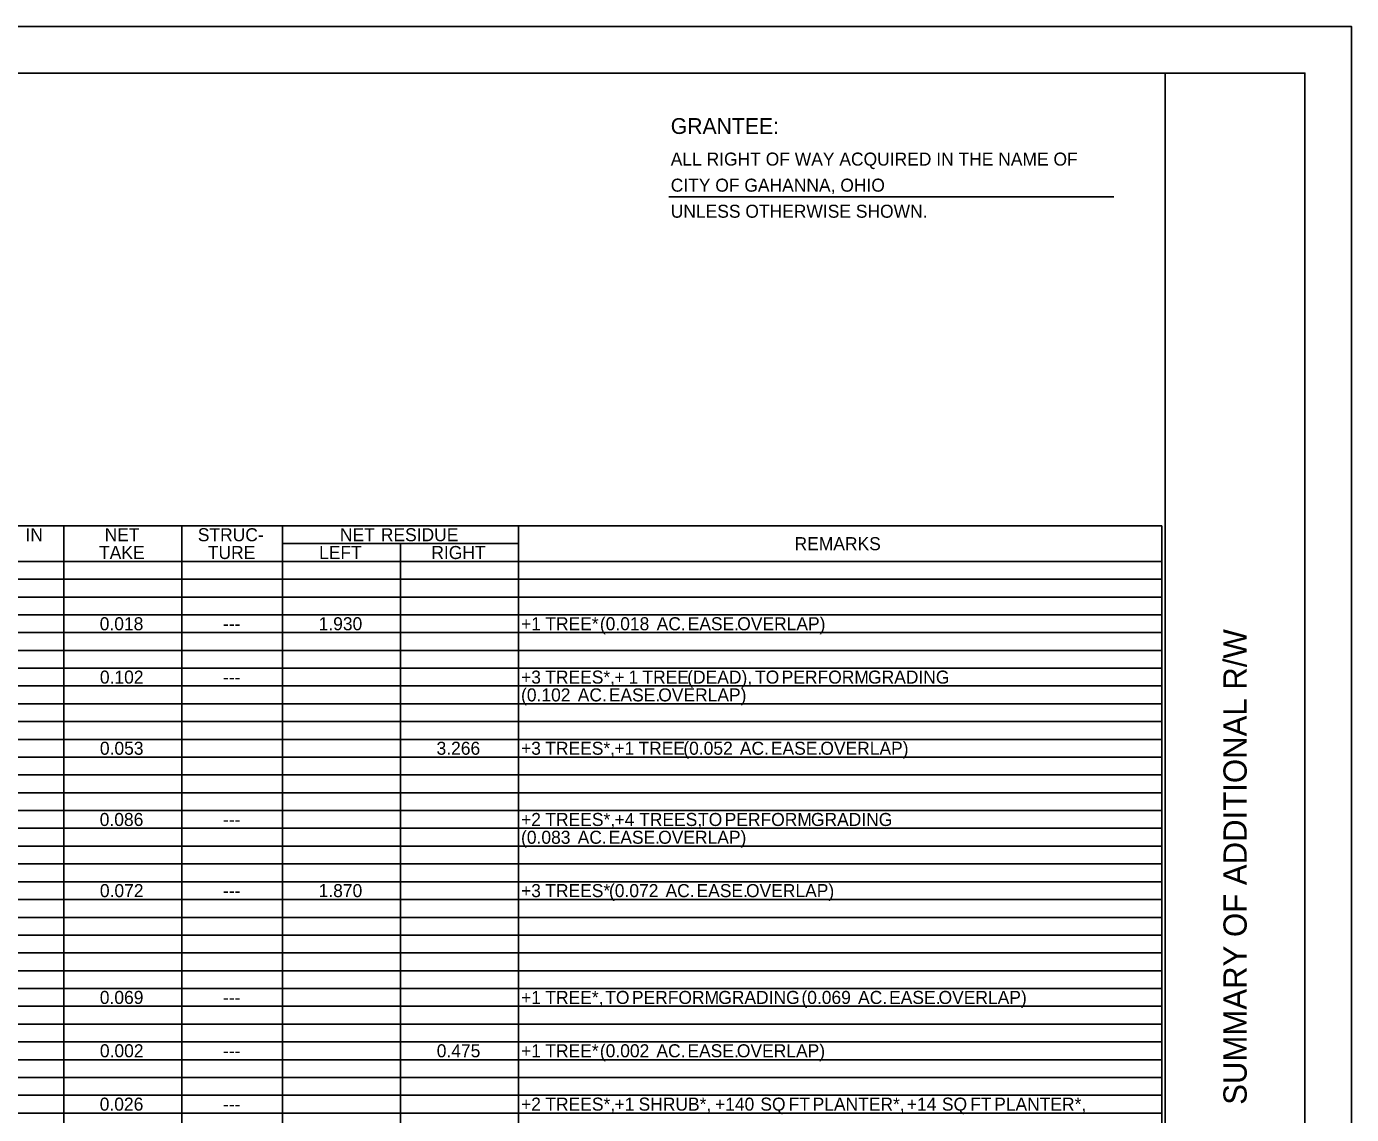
# Model space of a CAD drawing. Extents: x 0 to 34, y 0 to 22.
# Drawn here: x 19.78 to 34, y 10.32 to 22 of the extents above; entities that cross this region are included whole.
import ezdxf

# ---------------------------------------------------------------- set-up
doc = ezdxf.new("R2010")
doc.units = 0
for name, color, linetype in [('Default', 7, 'Continuous'), ('SH_Border', 7, 'Continuous'), ('SH_Cut_Line', 7, 'Continuous'), ('SH_Data', 7, 'Continuous'), ('SH_Text', 7, 'Continuous')]:
    doc.layers.add(name, color=color, linetype=linetype)

msp = doc.modelspace()

# ---------------------------------------------------------------- linework, layer by layer
at = {"layer": 'Default'}
for p, q in [((1.5, 16.637), (31.964, 16.637)), ((20.176, 5.554), (20.176, 16.637)), ((20.176, 16.255), (20.176, 16.637)), ((21.442, 5.554), (21.442, 16.637)), ((21.442, 16.255), (21.442, 16.637)), ((22.526, 5.554), (22.526, 16.637)), ((25.057, 5.554), (25.057, 16.637)), ((31.964, 5.554), (31.964, 16.637)), ((22.526, 16.446), (25.057, 16.446)), ((22.526, 16.255), (22.526, 16.446)), ((23.792, 5.554), (23.792, 16.446)), ((23.792, 16.255), (23.792, 16.446)), ((1.5, 16.255), (31.964, 16.255)), ((25.057, 16.255), (31.964, 16.255)), ((1.5, 16.064), (31.964, 16.064)), ((1.5, 15.873), (31.964, 15.873)), ((1.5, 15.682), (31.964, 15.682)), ((1.5, 15.491), (31.964, 15.491)), ((1.5, 15.3), (31.964, 15.3)), ((1.5, 15.109), (31.964, 15.109)), ((1.5, 14.918), (31.964, 14.918)), ((1.5, 14.726), (31.964, 14.726)), ((1.5, 14.535), (31.964, 14.535)), ((1.5, 14.344), (31.964, 14.344)), ((1.5, 14.153), (31.964, 14.153)), ((1.5, 13.962), (31.964, 13.962)), ((1.5, 13.771), (31.964, 13.771)), ((1.5, 13.58), (31.964, 13.58)), ((1.5, 13.389), (31.964, 13.389)), ((1.5, 13.198), (31.964, 13.198)), ((1.5, 13.007), (31.964, 13.007)), ((1.5, 12.815), (31.964, 12.815)), ((1.5, 12.624), (31.964, 12.624)), ((1.5, 12.433), (31.964, 12.433)), ((1.5, 12.242), (31.964, 12.242)), ((1.5, 12.051), (31.964, 12.051)), ((1.5, 11.86), (31.964, 11.86)), ((1.5, 11.669), (31.964, 11.669)), ((1.5, 11.478), (31.964, 11.478)), ((1.5, 11.287), (31.964, 11.287)), ((1.5, 11.096), (31.964, 11.096)), ((1.5, 10.904), (31.964, 10.904)), ((1.5, 10.713), (31.964, 10.713)), ((1.5, 10.522), (31.964, 10.522)), ((1.5, 10.331), (31.964, 10.331))]:
    msp.add_line(p, q, dxfattribs=at)
at = {"layer": 'SH_Border'}
msp.add_line((32, 0.5), (32, 21.5), dxfattribs=at)
msp.add_lwpolyline([(1.5, 21.5), (33.5, 21.5), (33.5, 0.5), (1.5, 0.5)], close=True, dxfattribs=at)
at = {"layer": 'SH_Cut_Line'}
msp.add_lwpolyline([(0, 0), (34, 0), (34, 22), (0, 22)], close=True, dxfattribs=at)
at = {"layer": 'SH_Text'}
msp.add_line((26.67, 20.17), (31.45, 20.17), dxfattribs=at)

# ---------------------------------------------------------------- texts
at = {"layer": 'Default'}
for s, p in [(' IN', (19.713, 16.472)), ('NET', (20.615, 16.472)), ('STRUC-', (21.615, 16.472)), ('NET', (23.141, 16.472)), (' RESIDUE', (23.528, 16.472)), ('REMARKS', (28.021, 16.376)), ('TAKE', (20.555, 16.281)), ('TURE', (21.723, 16.281)), ('LEFT', (22.917, 16.281)), ('RIGHT', (24.122, 16.281)), ('0.018', (20.562, 15.516)), ('1.930', (22.912, 15.516)), ('+1', (25.085, 15.516)), (' TREE*', (25.294, 15.516)), (' (0.018', (25.879, 15.516)), (' AC.', (26.489, 15.516)), (' EASE.', (26.822, 15.516)), (' OVERLAP)', (27.354, 15.516)), ('---', (21.886, 15.516)), ('0.102', (20.564, 14.943)), ('+3', (25.085, 14.943)), (' TREES*,', (25.293, 14.943)), (' 1', (26.187, 14.943)), (' TREE', (26.336, 14.943)), (' (DEAD),', (26.817, 14.943)), (' TO', (27.545, 14.943)), (' PERFORM', (27.831, 14.943)), (' GRADING', (28.758, 14.943)), ('---', (21.886, 14.943)), (' +', (26.035, 14.943)), ('(0.102', (25.085, 14.752)), (' AC.', (25.642, 14.752)), (' EASE.', (25.975, 14.752)), (' OVERLAP)', (26.506, 14.752)), ('0.053', (20.564, 14.179)), ('3.266', (24.178, 14.179)), ('+3', (25.085, 14.179)), (' TREES*,', (25.293, 14.179)), (' +1', (26.035, 14.179)), (' TREE', (26.294, 14.179)), (' (0.052', (26.775, 14.179)), (' AC.', (27.382, 14.179)), (' EASE.', (27.715, 14.179)), (' OVERLAP)', (28.246, 14.179)), ('0.086', (20.562, 13.414)), ('+2', (25.085, 13.414)), (' TREES*,', (25.294, 13.414)), (' +4', (26.036, 13.414)), (' TREES,', (26.301, 13.414)), (' TO', (26.933, 13.414)), (' PERFORM', (27.219, 13.414)), (' GRADING', (28.145, 13.414)), ('---', (21.886, 13.414)), ('(0.083', (25.085, 13.223)), (' OVERLAP)', (26.505, 13.223)), (' AC.', (25.641, 13.223)), (' EASE.', (25.974, 13.223)), ('0.072', (20.564, 12.65)), ('---', (21.886, 12.65)), ('1.870', (22.912, 12.65)), ('+3', (25.085, 12.65)), (' TREES*', (25.293, 12.65)), (' (0.072', (25.977, 12.65)), (' AC.', (26.584, 12.65)), (' EASE.', (26.917, 12.65)), (' OVERLAP)', (27.448, 12.65)), ('0.069', (20.563, 11.503)), ('---', (21.886, 11.503)), ('+1', (25.085, 11.503)), (' TREE*,', (25.294, 11.503)), (' TO', (25.937, 11.503)), (' PERFORM', (26.223, 11.503)), (' GRADING', (27.15, 11.503)), (' (0.069', (28.043, 11.503)), (' AC.', (28.651, 11.503)), (' EASE.', (28.984, 11.503)), (' OVERLAP)', (29.515, 11.503)), ('0.002', (20.564, 10.93)), ('---', (21.886, 10.93)), ('0.475', (24.18, 10.93)), ('+1', (25.085, 10.93)), (' TREE*', (25.294, 10.93)), (' (0.002', (25.879, 10.93)), (' AC.', (26.486, 10.93)), (' EASE.', (26.819, 10.93)), (' OVERLAP)', (27.35, 10.93)), ('0.026', (20.562, 10.357)), ('---', (21.886, 10.357)), ('+2', (25.085, 10.357)), (' TREES*,', (25.294, 10.357)), (' +1', (26.036, 10.357)), (' SHRUB*,', (26.295, 10.357)), (' +140', (27.115, 10.357)), (' SQ', (27.602, 10.357)), (' FT', (27.906, 10.357)), (' PLANTER*,', (28.163, 10.357)), (' +14', (29.174, 10.357)), (' SQ', (29.551, 10.357)), (' FT', (29.855, 10.357)), (' PLANTER*,', (30.112, 10.357))]:
    msp.add_text(s, height=0.14, dxfattribs=at).set_placement(p)
at = {"layer": 'SH_Data'}
msp.add_text('SUMMARY OF ADDITIONAL R/W', height=0.25, rotation=90, dxfattribs=at).set_placement((32.875, 10.42))
at = {"layer": 'SH_Text'}
for s, height, p in [('GRANTEE:', 0.17, (26.692, 20.846)), ('ALL RIGHT OF WAY ACQUIRED IN THE NAME OF', 0.14, (26.692, 20.506)), ('CITY OF GAHANNA, OHIO', 0.14, (26.692, 20.226)), ('UNLESS OTHERWISE SHOWN.', 0.14, (26.692, 19.946))]:
    msp.add_text(s, height=height, dxfattribs=at).set_placement(p)

doc.saveas('drawing.dxf')
